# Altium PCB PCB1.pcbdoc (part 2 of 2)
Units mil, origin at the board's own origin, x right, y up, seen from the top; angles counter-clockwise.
Board outline 4280 x 3470 mil, 2 copper layers (Top Layer, Bottom Layer); 101 components, 68 nets, 325 pads, 717 vias.
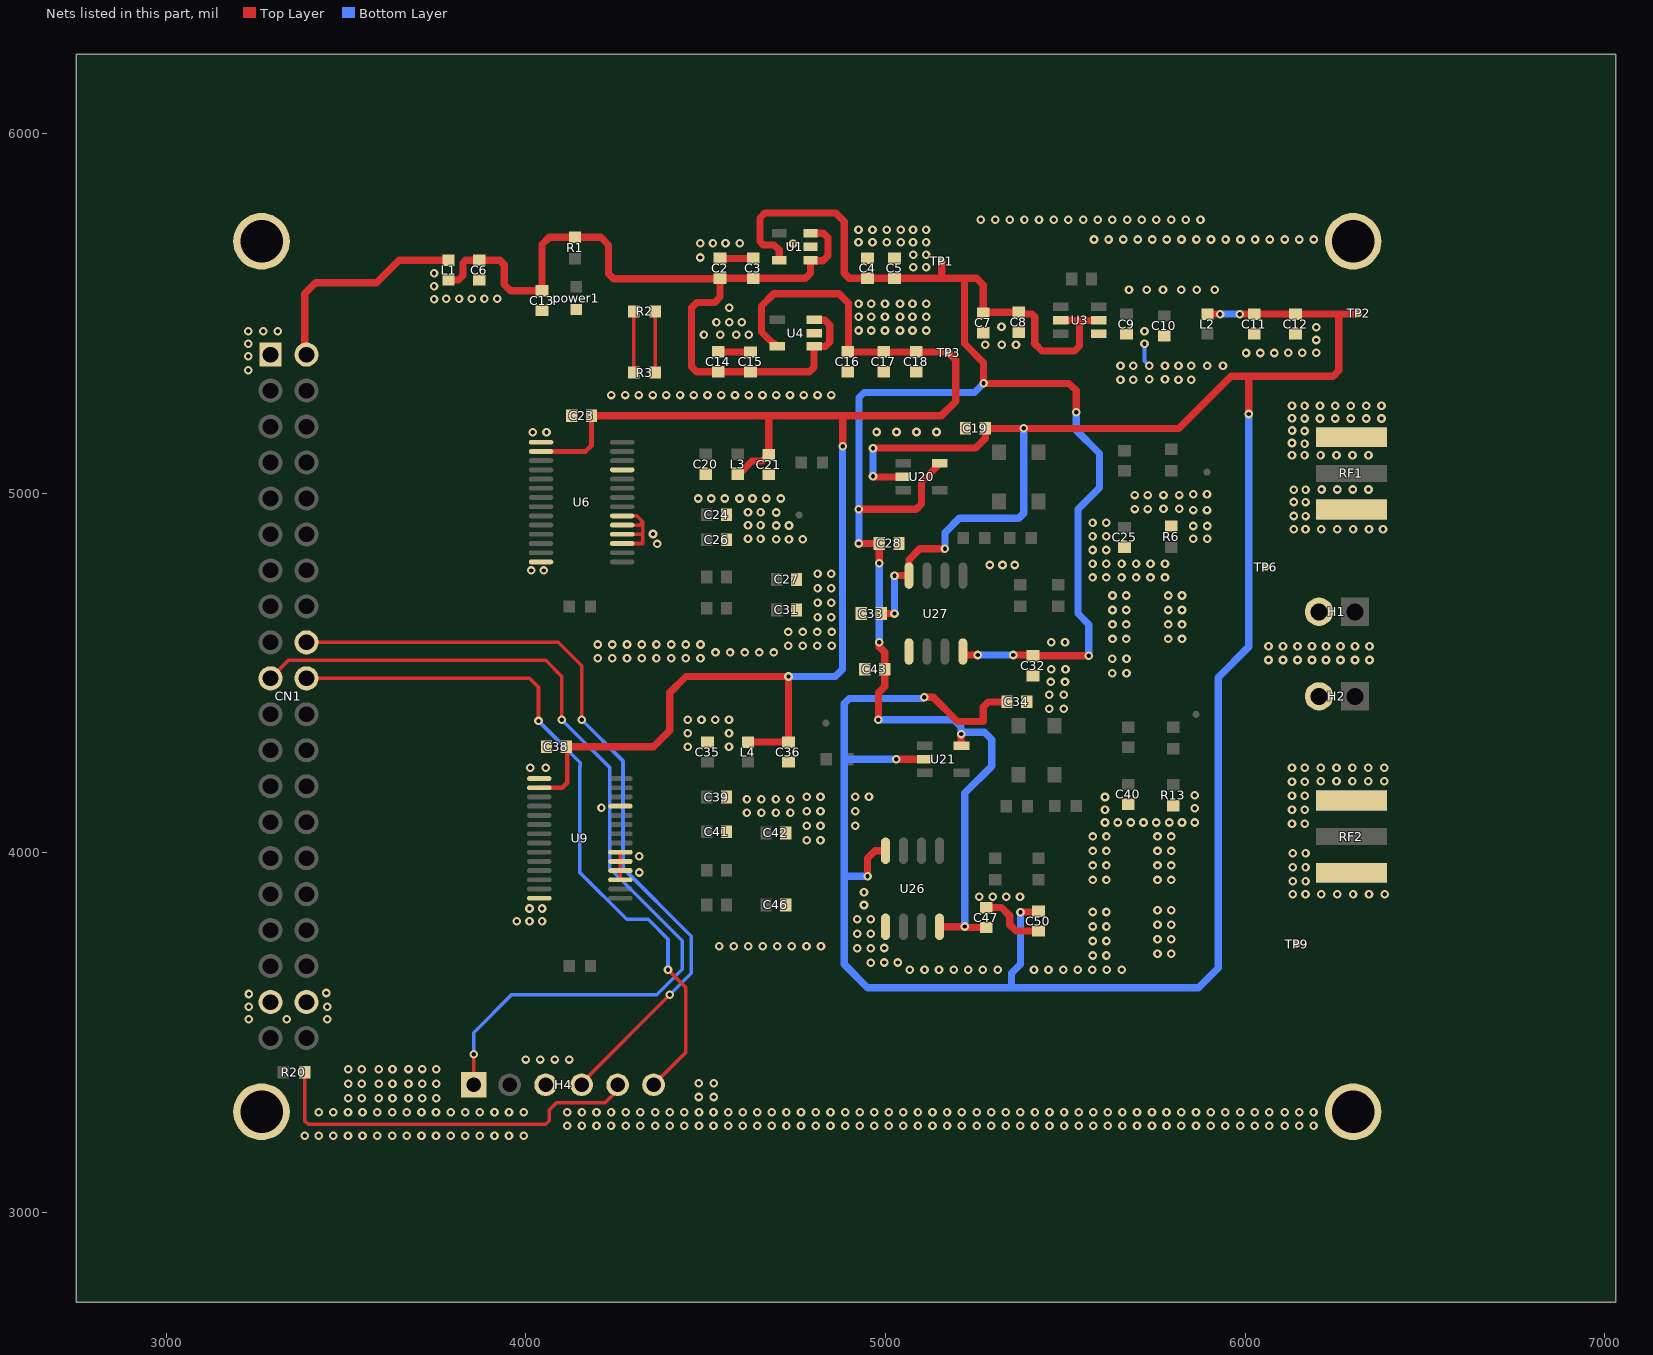
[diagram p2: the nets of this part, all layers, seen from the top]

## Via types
v1: diameter 24, hole 12, Top Layer to Bottom Layer, 717 vias

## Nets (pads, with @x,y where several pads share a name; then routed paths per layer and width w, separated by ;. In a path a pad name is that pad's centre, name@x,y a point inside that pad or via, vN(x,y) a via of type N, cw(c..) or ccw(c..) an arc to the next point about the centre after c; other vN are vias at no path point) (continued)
AGND: C2.1 C3.1 C4.1 C5.1 C6.1 C7.1 C8.1 C9.1 C10.1 C11.1 C12.1 C13.1 C14.1 C15.1 C16.1 C17.1 C18.1 C19.1 C20.2 C21.2 C23.2 C24.2 C25.1 C26.2 C27.2 C28.1 C31.2 C32.2 C33.2 C34.1 C35.2 C36.2 C38.2 C39.2 C40.1 C41.2 C42.2 C43.1 C46.2 C47.2 C50.2 CN1.1 CN1.37 CN1.38 H1.2 H2.2 H4.3 pad.1 power1.1 R2.1 R2.2 R3.1 R3.2 R6.2 R13.2 RF1.1 RF1.2 RF1.3 RF1.4 RF2.1 RF2.2 RF2.3 RF2.4 TP6.1 TP9.1 U1.2 U3.4 U4.2 U6.1 U6.14 U6.17 U6.18 U6.19 U6.20 U6.25 U9.1 U9.14 U9.17 U9.18 U9.19 U9.20 U9.25 U26.5 U27.5 | length 1133.1
  Top Layer w10: U9.14@4035.84,3875 U9.14@4037.18,3873.66 ; U9.17@4262.82,3924.84 U9.18@4262.82,3950.43 U9.19@4262.82,3976.02 U9.20@4262.82,4001.61 ; U6.17@4267.82,4859.84 4324.84,4859.84 4325,4860 4325,4888.65 ; U6.18@4267.82,4885.43 4321.78,4885.43 4325,4888.65 ; U6.19@4267.82,4911.02 4316.02,4911.02 4325,4920 ; U6.20@4267.82,4936.61 4308.39,4936.61 4325,4920 ; R3.1@4300.34,5335 R2.1@4300.34,5505 ; 4359.66,5355 R2.2@4359.66,5505 ; 4325,4888.65 4325,4920
  Top Layer w20: C14.1@4535,5392.56 C15.1@4624.46,5392.56 ; C2.1@4540,5652.56 C3.1@4631.88,5652.56 ; C47.2@5280,3847.56 5322.44,3847.56 5345,3825 5345,3800 5362.56,3782.44 C50.2@5425,3782.44
  Bottom Layer w10: v1(5720,5415) 5720,5367.22 v1(5732.75,5354.47)
  other v1: 3385,3213.26 3424.19,3213.26 3464.73,3213.26 3505.27,3213.26 3545.81,3213.26 3586.35,3213.26 3628.65,3213.26 3669.19,3213.26 3709.73,3213.26 3750.27,3213.26 3790.81,3213.26 3831.35,3213.26 3872.04,3213.26 3912.58,3213.26 3953.11,3213.26 3993.65,3213.26 4115.27,3240.97 4155.81,3240.97 4196.35,3240.97 4236.89,3240.97 4277.42,3240.97 4317.96,3240.97 4359.54,3240.97 4400.08,3240.97 4440.61,3240.97 4481.15,3240.97 4521.69,3240.97 4562.23,3240.97 4602.77,3240.97 4643.31,3240.97 4683.85,3240.97 4724.39,3240.97 4764.92,3240.97 4805.46,3240.97 4847.04,3240.97 4887.58,3240.97 4928.11,3240.97 4968.31,3240.97 5008.85,3240.97 5049.39,3240.97 5089.92,3240.97 5130.46,3240.97 5171,3240.97 5211.54,3240.97 5253.11,3240.97 5293.65,3240.97 5334.19,3240.97 5374.73,3240.97 5415.27,3240.97 5455.81,3240.97 5496.35,3240.97 5536.89,3240.97 5577.42,3240.97 5617.96,3240.97 5658.5,3240.97 5699.04,3240.97 5740.61,3240.97 5781.15,3240.97 5821.69,3240.97 5863.14,3240.97 5903.67,3240.97 5944.21,3240.97 5985.79,3240.97 6026.33,3240.97 6066.86,3240.97 6109.73,3240.97 6150.27,3240.97 6190,3240.97 3424.19,3279.03 3464.73,3279.03 3505.27,3279.03 3545.81,3279.03 3586.35,3279.03 3628.65,3279.03 3669.19,3279.03 3709.73,3279.03 3750.27,3279.03 3790.81,3279.03 3831.35,3279.03 3872.04,3279.03 3912.58,3279.03 3953.11,3279.03 3993.65,3279.03 4115.27,3279.03 4155.81,3279.03 4196.35,3279.03 4236.89,3279.03 4277.42,3279.03 4317.96,3279.03 4359.54,3279.03 4400.08,3279.03 4440.61,3279.03 4481.15,3279.03 4521.69,3279.03 4562.23,3279.03 4602.77,3279.03 4643.31,3279.03 4683.85,3279.03 4724.39,3279.03 4764.92,3279.03 4805.46,3279.03 4847.04,3279.03 4887.58,3279.03 4928.11,3279.03 4968.31,3279.03 5008.85,3279.03 5049.39,3279.03 5089.92,3279.03 5130.46,3279.03 5171,3279.03 5211.54,3279.03 5253.11,3279.03 5293.65,3279.03 5334.19,3279.03 5374.73,3279.03 5415.27,3279.03 5455.81,3279.03 5496.35,3279.03 5536.89,3279.03 5577.42,3279.03 5617.96,3279.03 5658.5,3279.03 5699.04,3279.03 5740.61,3279.03 5781.15,3279.03 5821.69,3279.03 5863.14,3279.03 5903.67,3279.03 5944.21,3279.03 5985.79,3279.03 6026.33,3279.03 6066.86,3279.03 6109.73,3279.03 6150.27,3279.03 6190,3279.03 3505.97,3317.5 3544.03,3317.5 3590.97,3317.5 3629.03,3317.5 3673.47,3317.57 3711.53,3317.57 3750.97,3317.5 4480.19,3320.97 4522.5,3320.97 3505.97,3358.04 3544.03,3358.04 3590.97,3358.04 3629.03,3358.04 3673.47,3358.11 3711.53,3358.11 3750.97,3358.04 4480.19,3359.03 4522.5,3359.03 3505.97,3398.58 3544.03,3398.58 3590.97,3398.58 3629.03,3398.58 3673.47,3398.64 3711.53,3398.64 3750.97,3398.58 3999.19,3425 4039.73,3425 4080.27,3425 4120.81,3425 3229.5,3537 3335.5,3537 3447.5,3537 3229.75,3572.25 3447.5,3572 3230,3607.5 3445,3610 5067.6,3675 5108.14,3675 5148.67,3675 5189.21,3675 5229.75,3675 5270.29,3675 5311.86,3675 5412.6,3675 5453.14,3675 5493.67,3675 5534.21,3675 5574.75,3675 5615.29,3675 5656.86,3675 4959.03,3694.54 4995.97,3694.85 5034.03,3694.85 5575.97,3714.54 5614.03,3714.54 5755.97,3719.54 5794.03,3719.54 4920.97,3734.85 4959.03,3734.85 4995.97,3735.15 4537.23,3740 4577.77,3740 4617.96,3740 4658.5,3740 4699.04,3740 4739.58,3740 4780.12,3740 4820.66,3740 5575.97,3754.85 5614.03,3754.85 5755.97,3759.85 5794.03,3759.85 4920.97,3775.15 4959.03,3775.15 5575.97,3795.15 5614.03,3795.15 5755.97,3800.15 5794.03,3800.15 3975,3810 4010,3810 4045,3810 4920.97,3815.46 4959.03,3815.46 5575.97,3835.46 5614.03,3835.46 5755.97,3840.46 5794.03,3840.46 4010,3845 4045,3845 4940,3854.69 5260.58,3877.68 5298.26,3877.68 5335.95,3877.68 5373.63,3877.68 6131.88,3884.47 6167.38,3884.47 6211.52,3884.47 6255.68,3884.47 6299.82,3884.47 6343.98,3884.47 6388.12,3884.47 4940,3890 6132.25,3921.06 6167.75,3921.06 5575.97,3924.54 5614.03,3924.54 5755.97,3924.54 5794.03,3924.54 4315,3945 6132.25,3960 6167.75,3960 5575.97,3964.85 5614.03,3964.85 5755.97,3964.85 5794.03,3964.85 4315,3990 6132.25,3998.94 6167.75,3998.94 5575.97,4005.15 5614.03,4005.15 5755.97,4005.15 5794.03,4005.15 4780.97,4034.54 4819.03,4034.54 5575.97,4045.46 5614.03,4045.46 5755.97,4045.46 5794.03,4045.46 4780.97,4074.85 4819.03,4074.85 4915.97,4074.85 6130,4080.75 6165.5,4080.75 5610,4084.03 5645.69,4084.03 5681.38,4084.03 5717.08,4084.03 5752.77,4084.03 5788.46,4084.03 5824.15,4084.03 5859.85,4084.03 4614.54,4110.97 4654.85,4110.97 4695.15,4110.97 4735.46,4110.97 4780.97,4115.15 4819.03,4115.15 4915.97,4115.15 5610,4120 6130,4119.69 6165.5,4119.69 5859.85,4124.03 4210,4125 4614.54,4149.03 4654.85,4149.03 4695.15,4149.03 4735.46,4149.03 4780.97,4155.46 4819.03,4155.46 4915.97,4155.46 4954.03,4155.46 5610,4155 6130,4158.62 6165.5,4158.62 5859.85,4160 6130,4197.56 6165.5,4197.56 6209.65,4198.5 6253.8,4198.5 6297.95,4198.5 6342.1,4198.5 6386.25,4198.5 6130,4236.5 6165.5,4236.5 6209.65,4236.5 6253.8,4236.5 6297.95,4236.5 6342.1,4236.5 6386.25,4236.5 4012.57,4236.81 4055,4236.81 4450,4294.85 4564.85,4295 4450,4332.22 4564.85,4332.58 4450,4369.59 4488.28,4369.59 4526.56,4369.59 4564.85,4369.59 5455,4400 5495,4400 5455,4439.68 5495,4439.68 5459.68,4475 5499.03,4475 5630,4499.35 5670,4499.35 5460.97,4510 5500.32,4510 6064.54,4535.97 6104.85,4535.97 6145.15,4535.97 6185.46,4535.97 6224.54,4535.97 6264.85,4535.97 6305.15,4535.97 6345.46,4535.97 5630,4539.03 5670,4539.03 4199.54,4540.97 4240.38,4540.97 4281.23,4540.97 4322.08,4540.97 4362.92,4540.97 4403.77,4540.97 4444.62,4540.97 4485.46,4540.97 4527.19,4557.03 4567.73,4557.03 4608.27,4557.03 4648.81,4557.03 4689.34,4557.03 6064.54,4574.03 6104.85,4574.03 6145.15,4574.03 6185.46,4574.03 6224.54,4574.03 6264.85,4574.03 6305.15,4574.03 6345.46,4574.03 4729.54,4575.97 4769.85,4575.97 4810.15,4575.97 4850.46,4575.97 4199.54,4579.03 4240.38,4579.03 4281.23,4579.03 4322.08,4579.03 4362.92,4579.03 4403.77,4579.03 4444.62,4579.03 4485.46,4579.03 5460.97,4585.15 5499.03,4585.15 5630.97,4594.54 5669.03,4594.54 5785.97,4594.54 5824.03,4594.54 4729.54,4614.03 4769.85,4614.03 4810.15,4614.03 4850.46,4614.03 5630.97,4634.85 5669.03,4634.85 5785.97,4634.85 5824.03,4634.85 4810.97,4654.54 4849.03,4654.54 5630.97,4675.15 5669.03,4675.15 5785.97,4675.15 5824.03,4675.15 4810.97,4694.85 4849.03,4694.85 5630.97,4715.46 5669.03,4715.46 5785.97,4715.46 5824.03,4715.46 4810.97,4735.15 4849.03,4735.15 5575.53,4765.53 5613.53,4765.53 5656.15,4765.53 5696.46,4765.53 5736.77,4765.53 5777.07,4765.53 4810.97,4775.46 4849.03,4775.46 4015,4785 4049.51,4785 5289.72,4800 5325,4800 5359.55,4800 5575.53,4803.59 5613.53,4803.59 5656.15,4803.59 5696.46,4803.59 5736.77,4803.59 5777.07,4803.59 5575.53,4841.64 5613.53,4841.64 4365.56,4858.67 4696.48,4872 4731.48,4872 4770,4872 4617.5,4873 4652.5,4873 5855.53,4873.1 5894.47,4873.1 5575.53,4879.7 5613.53,4879.7 4353.45,4886.37 6167.38,4899.47 6211.52,4899.47 6255.68,4899.47 6299.82,4899.47 6343.98,4899.47 6383.12,4899.47 6134.81,4899.73 5855.53,4908.6 5894.47,4908.6 4696.48,4910 4731.48,4910 4617.5,4911 4652.5,4911 5575.53,4917.75 5613.53,4917.75 6135.19,4936.33 6167.75,4936.06 4696.48,4946 4617.5,4947 4652.5,4947 5855.53,4952.75 5893.53,4952.75 5693.1,4955.53 5728.6,4955.53 5772.75,4956.47 5816.9,4956.47 6135.19,4975.27 6167.75,4975 4479,4985 4515,4985 4553,4985 4594,4985 4630,4985 4668,4985 4709,4985 5693.1,4994.47 5728.6,4994.47 5772.75,4994.47 5816.9,4994.47 5855.53,4996.9 5893.53,4996.9 6135.19,5009.2 6167.75,5008.94 6212.25,5010 6255.75,5010 6299.25,5010 6342.75,5010 6129.81,5105 6165,5105 6209.44,5105 6253.88,5105 6298.31,5105 6342.75,5105 6165,5137.25 6129.81,5139.44 4019.43,5169.34 4057.18,5169.34 4975,5170 5030.57,5170 5086.14,5170 5141.72,5170 6165,5172.75 6130.19,5173.88 6165,5207.25 6207.79,5207.25 6250.57,5207.25 6293.36,5207.25 6336.15,5207.25 6378.94,5207.25 6130,5208.31 6130,5242.75 6165,5242.75 6207.79,5242.75 6250.57,5242.75 6293.36,5242.75 6336.15,5242.75 6378.94,5242.75 4237.77,5272.5 4275.96,5272.5 4314.15,5272.5 4352.35,5272.5 4390.54,5272.5 4428.73,5272.5 4466.92,5272.5 4505.12,5272.5 4543.31,5272.5 4581.5,5272.5 4619.69,5272.5 4657.89,5272.5 4696.08,5272.5 4734.27,5272.5 4772.46,5272.5 4810.65,5272.5 4848.85,5272.5 5653.1,5315.53 5688.6,5315.53 5732.75,5316.47 5776.9,5316.47 5814.38,5315.53 5849.88,5315.53 3228.47,5341.32 5653.1,5354.47 5688.6,5354.47 5776.9,5354.47 5814.38,5354.47 5849.88,5354.47 5894.02,5354.47 5938.18,5354.47 3228.47,5380.8 6002.32,5389.47 6041.41,5389.47 6080.49,5389.47 6119.58,5390 6158.66,5390 6197.75,5390 5277.38,5412.5 5322.62,5412.5 5362.62,5412.5 3228.47,5415.45 6197.75,5425.52 4495,5440 4540,5440 4585,5440 4620,5440 3228.47,5450 3269.75,5450 3310,5450 5720,5450 4925,5452 4960,5452 4998.52,5452 5040,5452 5075,5452 5113.52,5452 6197.75,5461.04 5322.38,5462.5 4529.75,5475 4565,5475 4600.25,5475 4925,5490 4960,5490 4998.52,5490 5040,5490 5075,5490 5113.52,5490 4565,5515 4925,5526 4960,5526 4998.52,5526 5040,5526 5075,5526 5113.52,5526 3744.76,5539 3779,5540.24 3814.25,5540.24 3849.5,5540.24 3884.75,5540.24 3920,5540.24 5676.64,5565 5726.05,5565 5771.51,5565 5821.91,5565 5865.39,5565 5915,5565 3744.76,5575 3744.76,5611 5077.38,5627.5 5112.62,5627.5 4485,5655 5077.38,5662.5 5112.62,5662.5 4742.58,5693.31 4485,5695 4520,5695 4555,5695 4595,5695 4924.75,5697.5 4963.85,5697.5 5002.95,5697.5 5042.05,5697.5 5076.15,5697.5 5112.62,5697.5 5579.47,5705 5620.01,5705 5660.55,5705 5701.09,5705 5741.63,5705 5782.17,5705 5822.7,5705 5864.28,5705 5904.82,5705 5945.36,5705 5986.8,5705 6027.34,5705 6067.88,5705 6109.45,5705 6149.99,5705 6190.53,5705 4924.75,5732.5 4963.85,5732.5 5002.95,5732.5 5042.05,5732.5 5076.15,5732.5 5112.62,5732.5 5264.47,5760 5305.01,5760 5345.55,5760 5386.09,5760 5426.63,5760 5467.17,5760 5507.7,5760 5549.28,5760 5589.82,5760 5630.36,5760 5671.8,5760 5712.34,5760 5752.88,5760 5794.45,5760 5834.99,5760 5875.53,5760
KEY: CN1.19 H4.1 | length 2589.7
  Top Layer w10: CN1.19@3290,4485 3340,4535 4055,4535 4100,4490 v1(4100,4370) ; H4.1@3855,3355 v1(3855,3440)
  Bottom Layer w10: v1@3855,3450 3855,3500 3960,3605 4363.5,3605 4435,3676.5 4435,3755 4232.98,3957.02 4232.98,4237.02 v1(4100,4370)
RX: H4.5 R20.1 | length 1081.4
  Top Layer w10: R20.1@3384.66,3390 3384.66,3255 3394.66,3245 4055,3245 4065,3255 4065,3285 4085,3305 4220,3305 4255,3340 H4.5@4255,3355
STATE: CN1.20 H4.6 | length 1995.2
  Top Layer w10: CN1.20@3390,4485 4010,4485 4035,4460 v1@4035,4375 ; H4.6@4355,3355 4445,3445 4445,3625 v1(4395,3675)
  Bottom Layer w10: v1(4035,4366.6) 4151.23,4250.37 4151.23,4240.37 4150,4239.14 4150,3945 4280,3815 4340,3815 4395,3760 v1(4395,3675)
TX: CN1.18 H4.4 | length 2209.6
  Top Layer w10: CN1.18@3390,4585 4090,4585 4155,4520 v1(4155,4370) ; H4.4@4155,3355 4155,3360 v1(4400,3605)
  Bottom Layer w10: v1(4155,4370) 4270,4255 4270,3957.5 4460,3767.5 4460,3665 v1(4400,3605)
VCC: C16.2 C17.2 C18.2 C21.1 C23.1 C36.1 C38.1 L3.2 L4.2 TP3.1 U4.5 U6.2 U9.2 | length 4539.7
  Top Layer w13: U6.2@4042.18,5115.75 4165.75,5115.75 4182.56,5132.56 C23.1@4182.56,5215
  Top Layer w13.5: U9.2@4037.18,4180.75 4100.75,4180.75 4115,4195 4115,4292.56 C38.1@4112.56,4295
  Top Layer w20: C38.1@4112.56,4295 4355,4295 4400,4340 4400,4445 4445,4490 v1(4730,4490) C36.1@4730,4307.56 L4.2@4617.47,4307.56 ; C23.1@4182.56,5215 4676.93,5215 ; L3.2@4588.81,5052.44 4592.25,5052.44 4628.95,5089.14 4657.24,5089.14 C21.1@4675,5106.91 4675,5213.07 4676.93,5215 ; U4.5@4698.81,5407.6 4688.81,5417.6 4685.49,5417.6 4655,5448.09 4655,5520 4689.14,5554.14 4870.86,5554.14 4897.02,5527.98 4897.02,5392.5 C17.2@4979.94,5392.5 ; v1(4881.06,5130) 4881.06,5208.64 4887.42,5215 ; C17.2@4980,5392.56 C18.2@5085,5392.56 5172.86,5392.56 TP3.1@5175.48,5389.94 5195,5370.42 5195,5255 5155,5215 4887.42,5215 ; 4676.93,5215 4887.42,5215
  Bottom Layer w20: v1(4730,4490) 4860,4490 4880,4510 4880,5128.94 v1(4881.06,5130)
VCC+: C4.2 C5.2 C7.2 C8.2 C28.2 C32.1 C43.2 C47.1 TP1.1 U1.5 U3.2 U3.5 U20.5 U21.5 U26.8 U27.8 | length 6057.2
  Top Layer w20: U1.5@4704.27,5647.54 4704.27,5675.73 4690,5690 4660,5690 4650.86,5699.14 4650.86,5765 4665,5779.14 4860.86,5779.14 4885,5755 4885,5611.53 4899.14,5597.39 C4.2@4950,5597.44 C5.2@5025,5597.44 5152.64,5597.44 ; v1(4925.86,4860) C28.2@4982.44,4860 v1(4982.44,4805) ; v1(4925.86,4955) 5085,4955 5100,4970 5100,5031.22 U20.5@5151.19,5082.4 ; v1(4980,4370) 4980,4445 4997.56,4462.56 C43.2@4997.56,4510 4997.56,4557.44 4982.44,4572.56 v1(4982.44,4585) ; U26.8@5150,3794.39 5219.39,3794.39 v1(5220,3795) 5222.56,3792.44 C47.1@5280,3792.44 ; TP1.1@5156.17,5644.94 5156.17,5600.97 5152.64,5597.44 ; v1(5210,4330) 5210,4298.59 U21.5@5211.19,4297.4 ; U27.8@5219.39,4550 v1(5255.96,4550) ; C7.2@5271.65,5500.94 C7.2@5271.65,5502.56 ; v1(5355,4550) 5407.56,4550 C32.1@5410,4547.56 v1(5565,4547.56) ; U3.2@5486.85,5480 5538.3,5480 ; v1(5530,5225) 5530,5285 5510,5305 v1(5272.5,5305) 5272.5,5362.5 5219.26,5415.74 5219.26,5597.44 ; U3.5@5593.15,5480 5538.3,5480 ; 5152.64,5597.44 5219.26,5597.44 ; 5219.26,5597.44 5252.56,5597.44 5271.65,5578.35 C7.2@5271.65,5502.56 ; C7.2@5271.65,5502.56 5382.44,5502.56 5387.44,5497.56 5407.44,5497.56 5415,5490 5415,5415 5435,5395 5525,5395 5539.14,5409.14 5539.14,5479.15 5538.3,5480
  Bottom Layer w20: v1(4925.86,4860) v1(4925.86,4955) 4925.86,5265.86 4940,5280 5247.5,5280 v1(5272.5,5305) ; v1(4980,4370) 5190,4370 5210,4350 v1(5210,4330) 5215,4335 5275,4335 5295,4315 5295,4240.86 5220,4165.86 v1(5220,3795) ; v1(4982.44,4585) v1(4982.44,4805) ; v1(5255.96,4550) v1(5355,4550) ; v1(5530,5225) 5530,5175 5595,5110 5595,5015 5535,4955 5535,4665 5565,4635 v1(5565,4547.56)
VCC-: C11.2 C12.2 C19.2 C33.1 C34.2 C50.1 L2.2 TP2.1 U20.2 U21.2 U26.4 U27.4 | length 7681.3
  Top Layer w20: v1(4950,3935) 4950,3985 4970.61,4005.61 U26.4@5000,4005.61 ; v1(4965,5046.49) 4966.49,5045 U20.2@5048.81,5045 ; v1(4965,5125) 5250,5125 5277.56,5152.56 C19.2@5277.56,5180 ; C33.1@4987.56,4665 v1(5025,4665) ; v1(5025,4770.61) U27.4@5065,4770.61 5065,4815 5095,4845 v1(5165,4845) ; v1(5030,4260) U21.2@5108.81,4260 ; v1(5107.5,4432.5) 5132.5,4432.5 5200,4365 5271.5,4365 5271.5,4405 5285.65,4419.14 5336.58,4419.14 C34.2@5337.44,4420 ; C19.2@5292.56,5180 v1(5384.14,5180) 5815.65,5180 5960.65,5325 6005.56,5325 ; v1(5375,3835) C50.1@5422.44,3835 ; L2.2@5895,5497.56 v1(5930,5497.56) ; v1(5985,5497.56) C11.2@6025,5497.56 C12.2@6135,5497.56 ; v1(6010,5220) 6010,5320.56 6005.56,5325 ; C12.2@6137.5,5495.06 C12.2@6140,5492.56 ; C12.2@6140,5497.56 6260,5497.56 ; TP2.1@6312.56,5497.56 6260,5497.56 ; 6005.56,5325 6244.36,5325 6260,5340.64 6260,5497.56
  Bottom Layer w20: v1(4950,3935) 4885.93,3935 4885,3934.07 ; v1(4965,5046.49) v1(4965,5125) ; v1(5025,4665) v1(5025,4770.61) ; v1(5030,4260) 4887.67,4260 4885,4257.33 ; v1(5107.5,4432.5) 5104.14,4429.14 4899.14,4429.14 4885,4415 4885,4257.33 ; v1(5165,4845) 5165,4890 5205,4930 5370,4930 5384.14,4944.14 v1(5384.14,5180) ; v1(5375,3835) 5375,3690 5350,3665 5350,3626.02 5348.98,3625 ; v1(5930,5497.56) v1(5985,5497.56) ; v1(6010,5220) 6010,4572.56 5925,4487.56 5925,3680 5870,3625 5348.98,3625 ; 4885,3934.07 4885,3690 4950,3625 5348.98,3625 ; 4885,3934.07 4885,4257.33
VCC_5V: C2.2 C3.2 C6.2 C13.2 C14.2 C15.2 L1.2 R1.2 U1.1 U1.3 U4.1 U4.3 | length 2414.7
  Top Layer w20: L1.2@3785,5592.44 3812.45,5592.44 3825,5605 3825,5640 3832.56,5647.56 C6.2@3870,5647.56 3927.44,5647.56 3940,5635 3940,5580 3957.44,5562.56 C13.2@4045,5562.56 4045,5691.2 4065,5711.2 R1.2@4136.56,5711.2 4208.8,5711.2 4230,5690 4230,5610 4244.14,5595.86 4538.42,5595.86 C2.2@4540,5597.44 4540,5545 4525,5530 4475,5530 4460.86,5515.86 4460.86,5350.72 4474.14,5337.44 C14.2@4535,5337.44 C15.2@4624.52,5337.38 ; C2.2@4540.06,5597.38 C3.2@4631.94,5597.38 4777.38,5597.38 4790.89,5610.89 U1.1@4790.89,5647.55 4792.58,5645.86 4825.86,5645.86 4840,5660 4840,5710 4827.66,5722.34 U1.3@4790.89,5722.34 ; C15.2@4624.52,5337.38 4788.57,5337.38 4801.19,5350 U4.1@4801.19,5407.6 4832.6,5407.6 4845,5420 4845,5467.47 4830.86,5481.61 4801.98,5481.61 U4.3@4801.19,5482.4
VCC_IN: CN1.2 L1.1 | length 608.3
  Top Layer w20: CN1.2@3385,5385 3385,5555 3415,5585 3585,5585 3647.55,5647.56 L1.1@3785,5647.56
pads on no net: CN1.15 CN1.21 CN1.22 CN1.23 U1.4 U4.4

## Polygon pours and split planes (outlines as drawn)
AGND on Top Layer (solid, remove dead copper, pour order 0): 3105,5920 6520,5920 6520,3090 3105,3090
AGND on Bottom Layer (solid, remove dead copper, pour order 2): 3000,5970 6620,5970 6620,3000 3000,3000

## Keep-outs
Board Outline Layer:
  lines w10: 3150,3265 ccw(c3250,3265) 3250,3165 6315,3165 ccw(c6315,3265) 6415,3265 6415,5720 ccw(c6315,5720) 6315,5820 3250,5820 ccw(c3250,5720) 3150,5720 3150,3265

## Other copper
Top Layer:
  drawing of 361 lines, arcs and shapes, not listed
Bottom Layer:
  region net AGND: 5717.66,5362.49 5724.73,5369.56 5725.6,5368.82 5726.58,5368.19 5728.79,5367.27 5731.16,5366.71 5733.5,5366.45 5720.77,5353.72 5720.51,5356.06 5719.95,5358.43 5719.02,5360.64 5718.4,5361.62
  region net AGND: 5725,5398.66 5715,5398.66 5714.91,5399.8 5714.66,5400.93 5713.75,5403.15 5712.47,5405.22 5711,5407.06 5729,5407.06 5727.53,5405.22 5726.25,5403.15 5725.34,5400.93 5725.09,5399.8
  region net $1N12635: 4630,4038.67 4620,4038.67 4619.91,4039.81 4619.66,4040.94 4618.75,4043.16 4617.47,4045.23 4616,4047.07 4634,4047.07 4632.53,4045.23 4631.25,4043.16 4630.34,4040.94 4630.09,4039.81
  region net $1N12635: 4620,3998.41 4630,3998.41 4630.09,3997.27 4630.34,3996.14 4631.25,3993.92 4632.53,3991.85 4634,3990.01 4616,3990.01 4617.47,3991.85 4618.75,3993.92 4619.66,3996.14 4619.91,3997.27
  region net $1N12634: 4588.66,3900 4588.66,3910 4589.8,3910.09 4590.93,3910.34 4593.15,3911.25 4595.22,3912.53 4597.06,3914 4597.06,3896 4595.22,3897.47 4593.15,3898.75 4590.93,3899.66 4589.8,3899.91
  region net $1N12634: 4388.41,3910 4388.41,3900 4387.27,3899.91 4386.14,3899.66 4383.92,3898.75 4381.85,3897.47 4380.01,3896 4380.01,3914 4381.85,3912.53 4383.92,3911.25 4386.14,3910.34 4387.27,3910.09
  region net $1N3888: 4434.91,4913.02 4441.98,4920.09 4442.85,4919.35 4443.83,4918.73 4446.04,4917.8 4448.41,4917.24 4450.75,4916.98 4438.02,4904.25 4437.76,4906.59 4437.2,4908.96 4436.27,4911.17 4435.65,4912.15
  region net $1N3284: 4341.34,5120 4341.34,5110 4340.2,5109.91 4339.07,5109.66 4336.85,5108.75 4334.78,5107.47 4332.94,5106 4332.94,5124 4334.78,5122.53 4336.85,5121.25 4339.07,5120.34 4340.2,5120.09
  region net $1N3888: 4362.03,5020.04 4352.03,5020.04 4351.94,5021.17 4351.69,5022.31 4350.78,5024.52 4349.5,5026.59 4348.03,5028.44 4366.03,5028.44 4364.56,5026.59 4363.28,5024.52 4362.38,5022.31 4362.12,5021.17
  region net $1N12628: 4180.85,4041.96 4190.85,4040.68 4190.94,4039.54 4191.17,4038.42 4192.01,4036.24 4193.19,4034.18 4194.54,4032.28 4176.59,4033.56 4178.15,4035.33 4179.52,4037.42 4180.49,4039.68 4180.76,4040.82
  region net $1N12628: 4190.85,4133.82 4180.85,4133.82 4180.76,4134.96 4180.51,4136.09 4179.6,4138.31 4178.32,4140.38 4176.85,4142.22 4194.85,4142.22 4193.39,4140.38 4192.1,4138.31 4191.2,4136.09 4190.94,4134.96
  region net AD2_OTR: 3933.66,3850 3933.66,3860 3934.8,3860.09 3935.93,3860.34 3938.15,3861.25 3940.22,3862.53 3942.06,3864 3942.06,3846 3940.22,3847.47 3938.15,3848.75 3935.93,3849.66 3934.8,3849.91
  region net AD2_OE: 4348.54,3726.46 4341.46,3733.54 4342.14,3734.34 4342.58,3735.14 4342.85,3735.96 4342.97,3736.81 4343.02,3740.75 4355.75,3728.02 4351.81,3727.97 4350.96,3727.85 4350.14,3727.58 4349.34,3727.14
  region net AD2_OE: 3235,4168.66 3225,4168.66 3224.91,4169.8 3224.66,4170.93 3223.75,4173.15 3222.47,4175.22 3221,4177.06 3239,4177.06 3237.53,4175.22 3236.25,4173.15 3235.34,4170.93 3235.09,4169.8
  region net STATE: 4050.09,4358.59 4043.02,4351.51 4042.15,4352.25 4041.17,4352.88 4038.96,4353.8 4036.59,4354.36 4034.25,4354.63 4046.98,4367.35 4047.24,4365.01 4047.8,4362.64 4048.73,4360.43 4049.35,4359.45
  region net STATE: 4390,3691.34 4400,3691.34 4400.09,3690.2 4400.34,3689.07 4401.25,3686.85 4402.53,3684.78 4404,3682.94 4386,3682.94 4387.47,3684.78 4388.75,3686.85 4389.66,3689.07 4389.91,3690.2
  region net $1N17421: 5519.21,5082.86 5508.39,5079.54 5506.71,5080.93 5504.82,5082.04 5502.81,5082.97 5500.75,5083.78 5516.67,5092.19 5516.51,5091.09 5516.51,5089.86 5516.95,5087.24 5517.88,5084.77 5518.51,5083.72
  region net $1N17421: 5529.74,5058.19 5529.23,5072.84 5531.31,5070.9 5532.39,5070.08 5533.48,5069.45 5534.59,5069.04 5535.72,5068.92 5536.87,5069.15 5538.04,5069.77 5535.77,5052.34 5534.41,5053.8 5532.82,5055.32
  region net VCC: 4744.4,4500 4744.4,4480 4741.76,4479.91 4739.25,4479.69 4734.88,4479 4731.66,4478.31 4730,4478 4730,4502 4731.66,4501.69 4734.88,4501 4739.25,4500.31 4741.76,4500.09
  region net VCC: 4890,5114.54 4870,5116.66 4869.78,5120.63 4869.35,5123.87 4869.02,5127.1 4868.99,5128.95 4869.11,5131.06 4893.01,5128.94 4892.7,5126.52 4892.27,5124.63 4891.26,5121.75 4890.78,5120.4 4890.38,5118.86 4890.1,5116.97
  region net VCC+: 5269.39,5287.75 5255.25,5301.89 5257.06,5303.82 5258.66,5305.75 5261.27,5309.33 5263.06,5312.09 5264.01,5313.49 5280.99,5296.51 5279.59,5295.56 5276.83,5293.77 5273.25,5291.16 5271.32,5289.56
  region net VCC+: 4915.86,4874.4 4935.86,4874.4 4935.94,4871.76 4936.17,4869.25 4936.86,4864.88 4937.55,4861.66 4937.86,4860 4913.86,4860 4914.17,4861.66 4914.86,4864.88 4915.55,4869.25 4915.77,4871.76
  region net VCC+: 4992.44,4790.6 4972.44,4790.6 4972.35,4793.24 4972.13,4795.75 4971.44,4800.12 4970.75,4803.34 4970.44,4805 4994.44,4805 4994.13,4803.34 4993.44,4800.12 4992.75,4795.75 4992.53,4793.24
  region net VCC+: 4972.44,4599.4 4992.44,4599.4 4992.53,4596.76 4992.75,4594.25 4993.44,4589.88 4994.13,4586.66 4994.44,4585 4970.44,4585 4970.75,4586.66 4971.44,4589.88 4972.13,4594.25 4972.35,4596.76
  region net VCC+: 5270.36,4560 5270.36,4540 5267.71,4539.91 5265.21,4539.69 5260.83,4539 5257.61,4538.31 5255.96,4538 5255.96,4562 5257.61,4561.69 5260.83,4561 5265.21,4560.31 5267.71,4560.09
  region net VCC+: 5340.6,4540 5340.6,4560 5343.24,4560.09 5345.75,4560.31 5350.12,4561 5353.34,4561.69 5355,4562 5355,4538 5353.34,4538.31 5350.12,4539 5345.75,4539.69 5343.24,4539.91
  region net VCC+: 5540,5210.6 5520,5210.6 5519.91,5213.24 5519.69,5215.75 5519,5220.12 5518.31,5223.34 5518,5225 5542,5225 5541.69,5223.34 5541,5220.12 5540.31,5215.75 5540.09,5213.24
  region net VCC+: 5555,4561.96 5575,4561.96 5575.09,4559.32 5575.31,4556.81 5576,4552.44 5576.69,4549.22 5577,4547.56 5553,4547.56 5553.31,4549.22 5554,4552.44 5554.69,4556.81 5554.91,4559.32
  region net VCC+: 5210,3809.4 5230,3809.4 5230.09,3806.76 5230.31,3804.25 5231,3799.88 5231.69,3796.66 5232,3795 5208,3795 5208.31,3796.66 5209,3799.88 5209.69,3804.25 5209.91,3806.76
  region net KEY: 4115.09,4361.98 4108.02,4354.91 4107.15,4355.65 4106.17,4356.27 4103.96,4357.2 4101.59,4357.76 4099.25,4358.02 4111.98,4370.75 4112.24,4368.41 4112.8,4366.04 4113.73,4363.83 4114.35,4362.85
  region net KEY: 3850,3456.34 3860,3456.34 3860.09,3455.2 3860.34,3454.07 3861.25,3451.85 3862.53,3449.78 3864,3447.94 3846,3447.94 3847.47,3449.78 3848.75,3451.85 3849.66,3454.07 3849.91,3455.2
  region net TX: 4408.02,3620.09 4415.09,3613.02 4414.35,3612.15 4413.73,3611.17 4412.8,3608.96 4412.24,3606.59 4411.98,3604.25 4399.25,3616.98 4401.59,3617.24 4403.96,3617.8 4406.17,3618.73 4407.15,3619.35
  region net VCC-: 5385,3820.6 5365,3820.6 5364.91,3823.24 5364.69,3825.75 5364,3830.12 5363.31,3833.34 5363,3835 5387,3835 5386.69,3833.34 5386,3830.12 5385.31,3825.75 5385.09,3823.24
  region net VCC-: 5092.46,4419.14 5089.69,4439.14 5091.07,4439.05 5092.3,4438.84 5094.45,4438.41 5095.4,4438.36 5096.31,4438.54 5097.2,4439.04 5098.09,4439.95 5100.86,4422.51 5099.83,4422.9 5098.84,4422.77 5097.86,4422.26 5096.87,4421.52 5094.8,4419.93 5093.67,4419.36
  region net VCC-: 4935.6,3925 4935.6,3945 4938.24,3945.09 4940.75,3945.31 4945.12,3946 4948.34,3946.69 4950,3947 4950,3923 4948.34,3923.31 4945.12,3924 4940.75,3924.69 4938.24,3924.91
  region net VCC-: 5944.4,5507.56 5944.4,5487.56 5941.76,5487.47 5939.25,5487.24 5934.88,5486.56 5931.66,5485.87 5930,5485.56 5930,5509.56 5931.66,5509.24 5934.88,5508.56 5939.25,5507.87 5941.76,5507.64
  region net VCC-: 5970.6,5487.56 5970.6,5507.56 5973.24,5507.64 5975.75,5507.87 5980.12,5508.56 5983.34,5509.24 5985,5509.56 5985,5485.56 5983.34,5485.87 5980.12,5486.56 5975.75,5487.24 5973.24,5487.47
  region net VCC-: 5155,4859.4 5175,4859.4 5175.09,4856.76 5175.31,4854.25 5176,4849.88 5176.69,4846.66 5177,4845 5153,4845 5153.31,4846.66 5154,4849.88 5154.69,4854.25 5154.91,4856.76
  region net VCC-: 6020,5205.6 6000,5205.6 5999.91,5208.24 5999.69,5210.75 5999,5215.12 5998.31,5218.34 5998,5220 6022,5220 6021.69,5218.34 6021,5215.12 6020.31,5210.75 6020.09,5208.24
  region net VCC-: 5394.14,5165.6 5374.14,5165.6 5374.06,5168.24 5373.83,5170.75 5373.14,5175.12 5372.45,5178.34 5372.14,5180 5396.14,5180 5395.83,5178.34 5395.14,5175.12 5394.45,5170.75 5394.23,5168.24
  region net VCC+: 4915.86,4969.4 4935.86,4969.4 4935.94,4966.76 4936.17,4964.25 4936.86,4959.88 4937.55,4956.66 4937.86,4955 4913.86,4955 4914.17,4956.66 4914.86,4959.88 4915.55,4964.25 4915.77,4966.76
  region net VCC-: 4975,5110.6 4955,5110.6 4954.91,5113.24 4954.69,5115.75 4954,5120.12 4953.31,5123.34 4953,5125 4977,5125 4976.69,5123.34 4976,5120.12 4975.31,5115.75 4975.09,5113.24
  region net VCC-: 4955,5060.89 4975,5060.89 4975.09,5058.25 4975.31,5055.75 4976,5051.37 4976.69,5048.15 4977,5046.49 4953,5046.49 4953.31,5048.15 4954,5051.37 4954.69,5055.75 4954.91,5058.25
  region net $1N17421: 5228.54,5001.46 5221.46,5008.54 5222.14,5009.34 5222.58,5010.14 5222.85,5010.96 5222.97,5011.81 5223.02,5015.75 5235.75,5003.02 5231.81,5002.97 5230.96,5002.85 5230.14,5002.58 5229.34,5002.14
  region net $1N17421: 4996.34,5010 4996.34,5000 4995.2,4999.91 4994.07,4999.66 4991.85,4998.75 4989.78,4997.47 4987.94,4996 4987.94,5014 4989.78,5012.53 4991.85,5011.25 4994.07,5010.34 4995.2,5010.09
  region net VCC+: 4994.4,4380 4994.4,4360 4991.76,4359.91 4989.25,4359.69 4984.88,4359 4981.66,4358.31 4980,4358 4980,4382 4981.66,4381.69 4984.88,4381 4989.25,4380.31 4991.76,4380.09
  region net VCC+: 5200,4344.4 5220,4344.4 5220.09,4341.76 5220.31,4339.25 5221,4334.88 5221.69,4331.66 5222,4330 5198,4330 5198.31,4331.66 5199,4334.88 5199.69,4339.25 5199.91,4341.76
  region net VCC+: 5223.4,4345 5228.85,4325 5227.44,4325.1 5226.15,4325.34 5223.9,4325.84 5222.92,4325.9 5222.03,4325.7 5221.21,4325.13 5220.45,4324.11 5215,4340.91 5216.31,4340.57 5217.36,4340.79 5218.25,4341.41 5219.05,4342.28 5219.88,4343.23 5220.81,4344.11 5221.96,4344.75
  region net VCC-: 5015.6,4250 5015.6,4270 5018.24,4270.09 5020.75,4270.31 5025.12,4271 5028.34,4271.69 5030,4272 5030,4248 5028.34,4248.31 5025.12,4249 5020.75,4249.69 5018.24,4249.91
  region net VCC-: 4955,4250 ccw(c4955,4150) 4895,4230 4885,4257.33 4895,4290 ccw(c4955,4370) 4955,4270
  region net VCC-: 4950,3925 ccw(c4950,3839.38) 4895,3905 4885,3934.07 4895,3965 ccw(c4950,4030.62) 4950,3945
  region net AD2_OTR: 3435.56,4290 3435.56,4280 3432.92,4279.88 3430.66,4279.55 3428.73,4279.01 3427.09,4278.27 3425.69,4277.36 3424.48,4276.29 3423.4,4275.07 3422.42,4273.72 3418.47,4267.28 3415.79,4263.65 3414.11,4261.78 3412.13,4259.9 3412.13,4310.1 3414.11,4308.22 3415.79,4306.35 3418.47,4302.72 3422.42,4296.28 3423.4,4294.93 3424.48,4293.71 3425.69,4292.64 3427.09,4291.73 3428.73,4290.99 3430.66,4290.45 3432.92,4290.12
  region net $1N81228: 4382.02,4978.07 4392.02,4978.07 4392.11,4976.94 4392.36,4975.81 4393.27,4973.59 4394.55,4971.52 4396.02,4969.67 4378.02,4969.67 4379.48,4971.52 4380.77,4973.59 4381.67,4975.81 4381.93,4976.94
  region net $1N81228: 4392.02,5032.26 4382.02,5032.26 4381.93,5033.4 4381.67,5034.53 4380.77,5036.74 4379.48,5038.82 4378.02,5040.66 4396.02,5040.66 4394.55,5038.82 4393.27,5036.74 4392.36,5034.53 4392.11,5033.4
  region net $1N80652: 5321.34,4040 5321.34,4030 5320.2,4029.91 5319.07,4029.66 5316.85,4028.75 5314.78,4027.47 5312.94,4026 5312.94,4044 5314.78,4042.53 5316.85,4041.25 5319.07,4040.34 5320.2,4040.09
  region net $1N80652: 5505.73,4030 5505.73,4040 5506.87,4040.09 5508,4040.34 5510.22,4041.25 5512.29,4042.53 5514.13,4044 5514.13,4026 5512.29,4027.47 5510.22,4028.75 5508,4029.66 5506.87,4029.91
  region net VCC-: 5340,3665 cw(c5307.5,3665) 5320,3635 5348.98,3625 5380,3635 cw(c5392.5,3665) 5360,3665
  region net VCC-: 5035,4756.21 5015,4756.21 5014.91,4758.85 5014.69,4761.36 5014,4765.73 5013.31,4768.95 5013,4770.61 5037,4770.61 5036.69,4768.95 5036,4765.73 5035.31,4761.36 5035.09,4758.85
  region net VCC-: 5015,4679.4 5035,4679.4 5035.09,4676.76 5035.31,4674.25 5036,4669.88 5036.69,4666.66 5037,4665 5013,4665 5013.31,4666.66 5014,4669.88 5014.69,4674.25 5014.91,4676.76

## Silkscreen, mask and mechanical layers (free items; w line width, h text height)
Top Silkscreen Layer:
  drawing of 81 lines, arcs and shapes, not listed
  text "GND" at 3470,5345 h60
  text "VCC" at 3595,5345 h60
  text "OE1" at 3477.4,5250 h60
  text "D0" at 3617.5,5250 h60
  text "D2" at 3617.5,5150 h60
  text "D1" at 3497.45,5145 h60
  text "D3" at 3490.1,5050 h60
  text "D4" at 3616.7,5050 h60
  text "D5" at 3490.1,4950 h60
  text "D6" at 3618.35,4950 h60
  text "D7" at 3490.1,4850 h60
  text "D8" at 3617.5,4850.16 h60
  text "模拟输入RXA" at 6073.82,4835 h60
  text "D9" at 3490.95,4755 h60
  text "OR1" at 3603.95,4755 h60
  text "3PA1030" at 4048.3,4715 h50
  text "NC" at 3489.3,4650 h60
  text "CL1" at 3606.4,4650 h60
  text "RX" at 3490.1,4550 h60
  text "TX" at 3617.5,4550 h60
  text "KEY" at 3470.05,4450 h60
  text "ST" at 3617.5,4450 h60
  text "NC" at 3489.3,4345 h60
  text "NC" at 3616.7,4345 h60
  text "NC" at 3489.3,4250 h60
  text "OR2" at 3596.6,4250 h60
  text "OE2" at 3470.05,4145 h60
  text "D0" at 3617.5,4145 h60
  text "D1" at 3497.45,4050 h60
  text "D2" at 3617.5,4049.78 h60
  text "D3" at 3490.1,3949.78 h60
  text "D4" at 3616.7,3949.78 h60
  text "D5" at 3490.1,3849.78 h60
  text "D6" at 3618.35,3849.78 h60
  text "模拟输入RXB" at 6075,3820 h60
  text "3PA1030" at 4075,3785 h50
  text "D7" at 3490.1,3749.78 h60
  text "D8" at 3617.5,3749.93 h60
  text "D9" at 3490.95,3644.78 h60
  text "CL2" at 3599.05,3645 h60
  text "GND" at 3470,3550 h60
  text "GND" at 3597.4,3550 h60
  text "3V3" at 3469.2,3445 h60
  text "3V3" at 3596.6,3445 h60
  text "蓝牙接口" at 4135,3405 h75
  text "3PA_V1.0" at 5880,3395 h70
  text "RyanFPGA" at 4970,3385 h170
Bottom Silkscreen Layer:
  drawing of 8 lines, arcs and shapes, not listed
  text "模拟输入RXA" at 6410,4780 h100
  text "RyanFPGA" at 5045,4370 h280
  text "模拟输入RXB" at 6410,3760 h100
